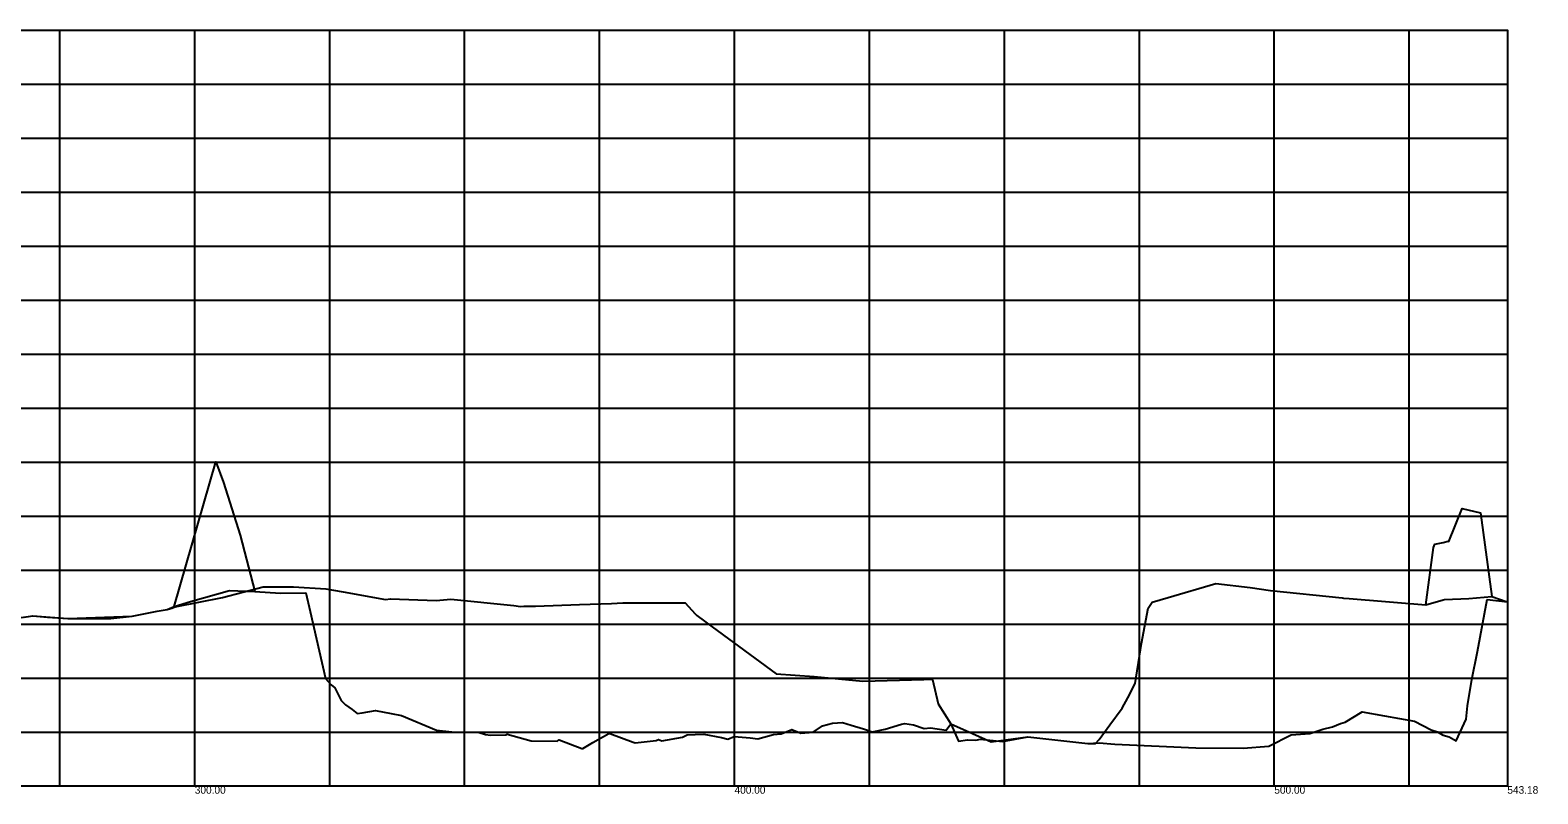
# Model space of a CAD drawing. Extents: x -1 to 1152, y 59 to 201.
# Drawn here: x 269.5 to 548.8, y 58.6 to 200 of the extents above; entities that cross this region are included whole.
import ezdxf

# ---------------------------------------------------------------- set-up
doc = ezdxf.new("R2010")
doc.units = 0
doc.layers.add('MAAMUDEL', color=7, linetype='Continuous')

msp = doc.modelspace()

# ---------------------------------------------------------------- linework, layer by layer
at = {"layer": 'MAAMUDEL'}
for p, q in [((275, 60), (275, 200)), ((300, 60), (300, 200)), ((325, 60), (325, 200)), ((350, 60), (350, 200)), ((375, 60), (375, 200)), ((400, 60), (400, 200)), ((425, 60), (425, 200)), ((450, 60), (450, 200)), ((475, 60), (475, 200)), ((500, 60), (500, 200)), ((525, 60), (525, 200)), ((0, 190), (543.18, 190)), ((0, 180), (543.18, 180)), ((0, 170), (543.18, 170)), ((0, 160), (543.18, 160)), ((0, 150), (543.18, 150)), ((0, 140), (543.18, 140)), ((0, 130), (543.18, 130)), ((0, 120), (543.18, 120)), ((0, 110), (543.18, 110)), ((0, 100), (543.18, 100)), ((0, 90), (543.18, 90)), ((0, 80), (543.18, 80)), ((0, 70), (543.18, 70))]:
    msp.add_line(p, q, dxfattribs=at)
msp.add_lwpolyline([(0, 60), (0, 200), (543.18, 200), (543.18, 60)], close=True, dxfattribs=at)
for points in [[(268.39, 91.3), (269.98, 91.54), (272.73, 91.32), (276.48, 91.02), (284.46, 91.04), (288.38, 91.51), (293.01, 92.4), (294.89, 92.69), (296.21, 93.25), (303.93, 120.05), (305.3, 116.25), (308.39, 106.48), (311.12, 96.07), (315.85, 95.71), (320.56, 95.81), (321.38, 92.32), (324.24, 79.93), (325.24, 78.77), (325.95, 78.21), (327.13, 75.86), (327.9, 75.09), (329.14, 74.22), (330.09, 73.47), (331, 73.59), (333.47, 74), (336.38, 73.48), (338.27, 73.06), (344.81, 70.39), (347.61, 70.04), (352.51, 69.97), (353.85, 69.56), (354.79, 69.43), (357.61, 69.5), (357.89, 69.63), (362.31, 68.41), (367.11, 68.36), (367.52, 68.56), (371.69, 67), (371.74, 66.93), (371.84, 66.98), (371.88, 66.95), (373.76, 68.08), (376.73, 69.77), (376.88, 69.75), (381.19, 68.14), (381.56, 68.04), (385.45, 68.46), (385.9, 68.64), (386.52, 68.41), (390.36, 69.06), (391.2, 69.52), (392.68, 69.56), (394.32, 69.6), (397.56, 69.03), (398.74, 68.68), (399.93, 69.22), (402.9, 68.92), (404.34, 68.79), (407.2, 69.54), (408.64, 69.67), (410.61, 70.5), (412.29, 69.81), (414.56, 70.02), (416.31, 71.17), (418.12, 71.64), (419.99, 71.81), (421.6, 71.3), (423.88, 70.61), (425.51, 70.09), (427.91, 70.56), (430.93, 71.5), (431.56, 71.59), (433.17, 71.37), (435.13, 70.66), (436.29, 70.8), (439.23, 70.34), (440.05, 71.52), (441.48, 68.33), (443.19, 68.6), (444.68, 68.49), (445.56, 68.69), (449.66, 68.29), (454.35, 69.12), (465.44, 67.91), (466.9, 67.89), (467.56, 68.66), (469.55, 71.33), (471.82, 74.47), (472.89, 76.38), (474.24, 79.03), (475.38, 86.44), (476.61, 92.95), (477.4, 94.09), (480.36, 94.94), (489.14, 97.52), (495.54, 96.8), (499.31, 96.22), (512.56, 94.86), (512.82, 94.79), (513.9, 94.76), (528.05, 93.57), (529.51, 104.18), (529.75, 104.8), (531.31, 105.13), (532.21, 105.39), (532.32, 105.32), (534.81, 111.44), (538.23, 110.63), (540.28, 95.13), (543.14, 94.14), (543.18, 94.14)], [(266.51, 91.04), (269.98, 91.54), (276.48, 91.02), (288.38, 91.51), (293.01, 92.4), (294.89, 92.69), (295.77, 92.97), (296.39, 93.19), (305.16, 94.96), (312.64, 96.93), (313.3, 96.94), (313.87, 96.94), (318.29, 96.94), (324.3, 96.52), (327.47, 95.96), (335.31, 94.58), (336.26, 94.7), (344.75, 94.36), (347.43, 94.6), (359.09, 93.43), (360.35, 93.29), (360.96, 93.34), (363.12, 93.34), (371.27, 93.63), (377.2, 93.81), (379.29, 93.94), (390.85, 93.92), (392.68, 91.94), (393, 91.6), (395.84, 89.5), (407.73, 80.82), (414.78, 80.29), (423.79, 79.47), (435.08, 79.75), (436.61, 79.83), (436.66, 79.74), (437.7, 75.23), (440.05, 71.52), (447.56, 68.22), (454.35, 69.12), (465.44, 67.91), (467.57, 68), (470.47, 67.79), (485.49, 67.1), (494.21, 67.03), (498.96, 67.43), (503.12, 69.48), (506.58, 69.75), (509, 70.53), (510.76, 71), (512.29, 71.6), (513.14, 71.86), (516.28, 73.77), (520.42, 73.05), (525.98, 72.01), (529.05, 70.43), (530.23, 70.08), (531.14, 69.51), (531.31, 69.46), (532.41, 69.14), (533.71, 68.4), (535.53, 72.41), (535.81, 74.9), (536.62, 79.75), (537.64, 84.94), (539.45, 94.58), (543.18, 94.16)], [(268.39, 91.3), (269.98, 91.54), (272.73, 91.32), (276.48, 91.02), (284.46, 91.04), (288.38, 91.51), (293.01, 92.4), (294.89, 92.69), (296.21, 93.25), (299.22, 94.21), (306.46, 96.21), (311.12, 96.07), (315.85, 95.71), (320.56, 95.81), (321.38, 92.32), (324.24, 79.93), (325.24, 78.77), (325.95, 78.21), (327.13, 75.86), (327.9, 75.09), (329.14, 74.22), (330.09, 73.47), (331, 73.59), (333.47, 74), (336.38, 73.48), (338.27, 73.06), (344.81, 70.39), (347.61, 70.04), (352.51, 69.97), (353.85, 69.56), (354.79, 69.43), (357.61, 69.5), (357.89, 69.63), (362.31, 68.41), (367.11, 68.36), (367.52, 68.56), (371.69, 67), (371.74, 66.93), (371.84, 66.98), (371.88, 66.95), (373.76, 68.08), (376.73, 69.77), (376.88, 69.75), (381.19, 68.14), (381.56, 68.04), (385.45, 68.46), (385.9, 68.64), (386.52, 68.41), (390.36, 69.06), (391.2, 69.52), (392.68, 69.56), (394.32, 69.6), (397.56, 69.03), (398.74, 68.68), (399.93, 69.22), (402.9, 68.92), (404.34, 68.79), (407.2, 69.54), (408.64, 69.67), (410.61, 70.5), (412.29, 69.81), (414.56, 70.02), (416.31, 71.17), (418.12, 71.64), (419.99, 71.81), (421.6, 71.3), (423.88, 70.61), (425.51, 70.09), (427.91, 70.56), (430.93, 71.5), (431.56, 71.59), (433.17, 71.37), (435.13, 70.66), (436.29, 70.8), (439.23, 70.34), (440.05, 71.52), (441.48, 68.33), (443.19, 68.6), (444.68, 68.49), (445.56, 68.69), (449.66, 68.29), (454.35, 69.12), (465.44, 67.91), (466.9, 67.89), (467.56, 68.66), (469.55, 71.33), (471.82, 74.47), (472.89, 76.38), (474.24, 79.03), (475.38, 86.44), (476.61, 92.95), (477.4, 94.09), (480.36, 94.94), (489.14, 97.52), (495.54, 96.8), (499.31, 96.22), (512.56, 94.86), (512.82, 94.79), (513.9, 94.76), (528.05, 93.57), (531.31, 94.49), (531.56, 94.56), (536.07, 94.76), (540.28, 95.13), (543.14, 94.14), (543.18, 94.14)]]:
    msp.add_lwpolyline(points, dxfattribs=at)

# ---------------------------------------------------------------- texts
for s, p in [('300.00', (300, 58.6)), ('400.00', (400, 58.6)), ('500.00', (500, 58.6)), ('543.18', (543.18, 58.6))]:
    msp.add_text(s, height=1.4, dxfattribs=at).set_placement(p)

doc.saveas('drawing.dxf')
